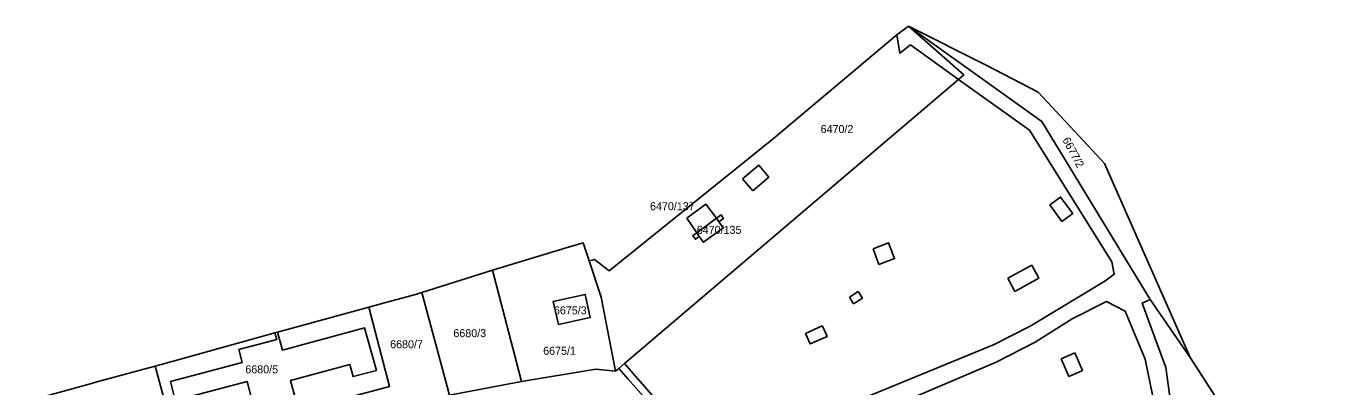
# Model space of a CAD drawing. Extents: x -266199 to -261993, y -1239047 to -1235108.
# Drawn here: x -263762 to -263435, y -1235757.7 to -1235667.6 of the extents above; entities that cross this region are included whole.
import ezdxf

# ---------------------------------------------------------------- set-up
doc = ezdxf.new("R2010")
doc.units = 0
for name, color, linetype in [('body_kn', 7, 'Continuous'), ('kladpar_druhypozemkov', 7, 'Continuous'), ('kladpar_hranice', 7, 'Continuous'), ('kladpar_parcelnecisla', 7, 'Continuous'), ('kladpar_plochy', 7, 'Continuous'), ('kladpar_sipky', 7, 'Continuous'), ('zappar_hrandruhpozemk', 7, 'Continuous')]:
    doc.layers.add(name, color=color, linetype=linetype)

msp = doc.modelspace()

# ---------------------------------------------------------------- linework, layer by layer
at = {"layer": 'body_kn'}
for p, q in [((-263544.41, -1235669.73), (-263544.41, -1235669.73)), ((-263544.41, -1235669.73), (-263544.41, -1235669.73)), ((-263541.53, -1235667.57), (-263541.53, -1235667.57)), ((-263541.53, -1235667.57), (-263541.53, -1235667.57)), ((-263541.05, -1235672.26), (-263541.05, -1235672.26)), ((-263543.64, -1235674.36), (-263543.64, -1235674.36)), ((-263527.67, -1235679.77), (-263527.67, -1235679.77)), ((-263522.1, -1235677.36), (-263522.1, -1235677.36)), ((-263528.99, -1235680.89), (-263528.99, -1235680.89)), ((-263528.99, -1235680.89), (-263528.99, -1235680.89)), ((-263509.13, -1235684.08), (-263509.13, -1235684.08)), ((-263508.24, -1235691.41), (-263508.24, -1235691.41)), ((-263575.26, -1235695.67), (-263575.26, -1235695.67)), ((-263511.25, -1235693.59), (-263511.25, -1235693.59)), ((-263578.93, -1235702.32), (-263578.93, -1235702.32)), ((-263494.46, -1235699.85), (-263494.46, -1235699.85)), ((-263492.55, -1235701.9), (-263492.55, -1235701.9)), ((-263582.95, -1235705.7), (-263582.95, -1235705.7)), ((-263582.95, -1235705.7), (-263582.95, -1235705.7)), ((-263576.41, -1235705.35), (-263576.41, -1235705.35)), ((-263580.4, -1235708.7), (-263580.4, -1235708.7)), ((-263592.11, -1235712.08), (-263592.11, -1235712.08)), ((-263506.17, -1235712.23), (-263506.17, -1235712.23)), ((-263503.5, -1235710.28), (-263503.5, -1235710.28)), ((-263596.91, -1235715.61), (-263596.91, -1235715.61)), ((-263596.91, -1235715.61), (-263596.91, -1235715.61)), ((-263589.52, -1235715.58), (-263589.52, -1235715.58)), ((-263589.52, -1235715.58), (-263589.52, -1235715.58)), ((-263588.35, -1235714.73), (-263588.35, -1235714.73)), ((-263587.7, -1235715.63), (-263587.7, -1235715.63)), ((-263500.47, -1235714.43), (-263500.47, -1235714.43)), ((-263588.9, -1235716.51), (-263588.9, -1235716.51)), ((-263587.81, -1235718.01), (-263587.81, -1235718.01)), ((-263503.17, -1235716.37), (-263503.17, -1235716.37)), ((-263503.17, -1235716.37), (-263503.17, -1235716.37)), ((-263622.79, -1235721.75), (-263622.79, -1235721.75)), ((-263595.42, -1235719.94), (-263595.42, -1235719.94)), ((-263594.77, -1235720.82), (-263594.77, -1235720.82)), ((-263594.39, -1235719.2), (-263594.39, -1235719.2)), ((-263594.39, -1235719.2), (-263594.39, -1235719.2)), ((-263593.83, -1235720.13), (-263593.83, -1235720.13)), ((-263592.76, -1235721.6), (-263592.76, -1235721.6)), ((-263546.54, -1235721.72), (-263546.54, -1235721.72)), ((-263627.04, -1235723.02), (-263627.04, -1235723.02)), ((-263550.33, -1235723.24), (-263550.33, -1235723.24)), ((-263545.01, -1235725.63), (-263545.01, -1235725.63)), ((-263645.42, -1235728.54), (-263645.42, -1235728.54)), ((-263645.42, -1235728.54), (-263645.42, -1235728.54)), ((-263621.28, -1235726.23), (-263621.28, -1235726.23)), ((-263621.28, -1235726.23), (-263621.28, -1235726.23)), ((-263620.53, -1235726.03), (-263620.53, -1235726.03)), ((-263619.96, -1235725.88), (-263619.96, -1235725.88)), ((-263616.31, -1235728.73), (-263616.31, -1235728.73)), ((-263548.93, -1235727.17), (-263548.93, -1235727.17)), ((-263548.93, -1235727.17), (-263548.93, -1235727.17)), ((-263510.66, -1235727.33), (-263510.66, -1235727.33)), ((-263490.71, -1235726.49), (-263490.71, -1235726.49)), ((-263516.68, -1235730.6), (-263516.68, -1235730.6)), ((-263508.99, -1235730.58), (-263508.99, -1235730.58)), ((-263492.43, -1235731.3), (-263492.43, -1235731.3)), ((-263490.11, -1235729.58), (-263490.11, -1235729.58)), ((-263664.65, -1235734.66), (-263664.65, -1235734.66)), ((-263663.09, -1235734.16), (-263663.09, -1235734.16)), ((-263663.09, -1235734.16), (-263663.09, -1235734.16)), ((-263622.29, -1235734.63), (-263622.29, -1235734.63)), ((-263622.29, -1235734.63), (-263622.29, -1235734.63)), ((-263618.29, -1235735.33), (-263618.29, -1235735.33)), ((-263556.25, -1235735.3), (-263556.25, -1235735.3)), ((-263554.06, -1235733.87), (-263554.06, -1235733.87)), ((-263514.91, -1235733.87), (-263514.91, -1235733.87)), ((-263514.91, -1235733.87), (-263514.91, -1235733.87)), ((-263676.38, -1235737.84), (-263676.38, -1235737.84)), ((-263672.4, -1235736.76), (-263672.4, -1235736.76)), ((-263630.28, -1235736.36), (-263630.28, -1235736.36)), ((-263555.27, -1235736.99), (-263555.27, -1235736.99)), ((-263555.27, -1235736.99), (-263555.27, -1235736.99)), ((-263553.03, -1235735.56), (-263553.03, -1235735.56)), ((-263492.02, -1235736.4), (-263492.02, -1235736.4)), ((-263483.11, -1235736.81), (-263483.11, -1235736.81)), ((-263481.16, -1235735.9), (-263481.16, -1235735.9)), ((-263621.08, -1235740.41), (-263621.08, -1235740.41)), ((-263500.63, -1235740.71), (-263500.63, -1235740.71)), ((-263487.38, -1235738.85), (-263487.38, -1235738.85)), ((-263699.81, -1235744.23), (-263699.81, -1235744.23)), ((-263699.16, -1235744.05), (-263699.16, -1235744.05)), ((-263693.7, -1235742.53), (-263693.7, -1235742.53)), ((-263677.42, -1235742.99), (-263677.42, -1235742.99)), ((-263628.96, -1235742.11), (-263628.96, -1235742.11)), ((-263567.22, -1235744.43), (-263567.22, -1235744.43)), ((-263567.22, -1235744.43), (-263567.22, -1235744.43)), ((-263563.05, -1235742.47), (-263563.05, -1235742.47)), ((-263562.84, -1235742.93), (-263562.84, -1235742.93)), ((-263561.85, -1235745.14), (-263561.85, -1235745.14)), ((-263511.14, -1235742.6), (-263511.14, -1235742.6)), ((-263708.85, -1235748.43), (-263708.85, -1235748.43)), ((-263699.37, -1235745.93), (-263699.37, -1235745.93)), ((-263697.95, -1235748.55), (-263697.95, -1235748.55)), ((-263566.11, -1235746.99), (-263566.11, -1235746.99)), ((-263520.12, -1235747.13), (-263520.12, -1235747.13)), ((-263509.88, -1235746.59), (-263509.88, -1235746.59)), ((-263723.4, -1235750.79), (-263723.4, -1235750.79)), ((-263708, -1235751.65), (-263708, -1235751.65)), ((-263519.61, -1235751.6), (-263519.61, -1235751.6)), ((-263503.34, -1235750.71), (-263503.34, -1235750.71)), ((-263503.34, -1235750.71), (-263503.34, -1235750.71)), ((-263499.96, -1235749.23), (-263499.96, -1235749.23)), ((-263482.36, -1235750.8), (-263482.36, -1235750.8)), ((-263471.12, -1235750.36), (-263471.12, -1235750.36)), ((-263729.77, -1235752.53), (-263729.77, -1235752.53)), ((-263729.77, -1235752.53), (-263729.77, -1235752.53)), ((-263681.11, -1235752.15), (-263681.11, -1235752.15)), ((-263674.46, -1235753.68), (-263674.46, -1235753.68)), ((-263619.66, -1235753.32), (-263619.66, -1235753.32)), ((-263614.69, -1235753.79), (-263614.69, -1235753.79)), ((-263614.69, -1235753.79), (-263614.69, -1235753.79)), ((-263613.92, -1235753.14), (-263613.92, -1235753.14)), ((-263613.92, -1235753.14), (-263613.92, -1235753.14)), ((-263612.49, -1235751.92), (-263612.49, -1235751.92)), ((-263612.49, -1235751.92), (-263612.49, -1235751.92)), ((-263499.69, -1235754.37), (-263499.69, -1235754.37)), ((-263498.03, -1235753.64), (-263498.03, -1235753.64)), ((-263477.26, -1235752.88), (-263477.26, -1235752.88)), ((-263745.66, -1235756.87), (-263745.66, -1235756.87)), ((-263744.32, -1235756.5), (-263744.32, -1235756.5)), ((-263725.93, -1235756.38), (-263725.93, -1235756.38)), ((-263706.75, -1235756.38), (-263706.75, -1235756.38)), ((-263695.92, -1235756.17), (-263695.92, -1235756.17)), ((-263680.27, -1235755.19), (-263680.27, -1235755.19)), ((-263671.15, -1235757.69), (-263671.15, -1235757.69)), ((-263638.19, -1235756.44), (-263638.19, -1235756.44)), ((-263611.54, -1235755.83), (-263611.54, -1235755.83)), ((-263609.19, -1235755.69), (-263609.19, -1235755.69)), ((-263501.42, -1235755.13), (-263501.42, -1235755.13))]:
    msp.add_line(p, q, dxfattribs=at)
at = {"layer": 'kladpar_druhypozemkov'}
for p, q in [((-263558.66, -1235691.69), (-263558.66, -1235691.69)), ((-263498.61, -1235698.96), (-263498.61, -1235698.96)), ((-263579.82, -1235705.75), (-263579.82, -1235705.75)), ((-263593.28, -1235715.41), (-263593.28, -1235715.41)), ((-263503.02, -1235713.35), (-263503.02, -1235713.35)), ((-263590.24, -1235717.9), (-263590.24, -1235717.9)), ((-263547.74, -1235724.66), (-263547.74, -1235724.66)), ((-263512.6, -1235730.61), (-263512.6, -1235730.61)), ((-263554.33, -1235735.22), (-263554.33, -1235735.22)), ((-263625.26, -1235737.02), (-263625.26, -1235737.02)), ((-263666.56, -1235745.29), (-263666.56, -1235745.29)), ((-263650.5, -1235742.91), (-263650.5, -1235742.91)), ((-263564.63, -1235744.59), (-263564.63, -1235744.59)), ((-263628.87, -1235747.41), (-263628.87, -1235747.41)), ((-263702.13, -1235751.86), (-263702.13, -1235751.86)), ((-263500.36, -1235752.78), (-263500.36, -1235752.78))]:
    msp.add_line(p, q, dxfattribs=at)
at = {"layer": 'kladpar_hranice'}
for points in [[(-263621.28, -1235726.23), (-263620.53, -1235726.03), (-263619.96, -1235725.88), (-263616.31, -1235728.73), (-263575.26, -1235695.67), (-263544.41, -1235669.73), (-263541.53, -1235667.57)], [(-263541.53, -1235667.57), (-263527.67, -1235679.77), (-263528.99, -1235680.89), (-263612.49, -1235751.92), (-263613.92, -1235753.14), (-263614.69, -1235753.79)], [(-263614.69, -1235753.79), (-263613.92, -1235753.14), (-263612.49, -1235751.92), (-263528.99, -1235680.89), (-263527.67, -1235679.77), (-263541.53, -1235667.57)], [(-263541.53, -1235667.57), (-263522.1, -1235677.36), (-263509.13, -1235684.08), (-263494.46, -1235699.85), (-263492.55, -1235701.9), (-263471.12, -1235750.36), (-263481.16, -1235735.9), (-263508.24, -1235691.41), (-263541.53, -1235667.57)], [(-263541.53, -1235667.57), (-263508.24, -1235691.41), (-263481.16, -1235735.9), (-263471.12, -1235750.36), (-263458.67, -1235769.77), (-263457.2, -1235774.82), (-263442.51, -1235813.86), (-263440.38, -1235820.49), (-263438.16, -1235827.4), (-263435, -1235836.54), (-263491.16, -1235848.11), (-263475.82, -1235844.22), (-263481.69, -1235826.93), (-263483.75, -1235820.84), (-263489.59, -1235803.64), (-263491.33, -1235798.48), (-263500.09, -1235772.67), (-263519.04, -1235777.56)], [(-263596.91, -1235715.61), (-263592.11, -1235712.08), (-263589.52, -1235715.58), (-263594.39, -1235719.2), (-263596.91, -1235715.61)], [(-263596.91, -1235715.61), (-263594.39, -1235719.2), (-263595.42, -1235719.94), (-263594.77, -1235720.82), (-263593.83, -1235720.13), (-263592.76, -1235721.6), (-263587.81, -1235718.01), (-263588.9, -1235716.51), (-263587.7, -1235715.63), (-263588.35, -1235714.73), (-263589.52, -1235715.58), (-263592.11, -1235712.08), (-263596.91, -1235715.61)], [(-263589.52, -1235715.58), (-263588.35, -1235714.73), (-263587.7, -1235715.63), (-263588.9, -1235716.51), (-263587.81, -1235718.01), (-263592.76, -1235721.6), (-263593.83, -1235720.13), (-263594.77, -1235720.82), (-263595.42, -1235719.94), (-263594.39, -1235719.2), (-263589.52, -1235715.58)], [(-263645.42, -1235728.54), (-263627.04, -1235723.02), (-263622.79, -1235721.75), (-263621.28, -1235726.23), (-263618.29, -1235735.33), (-263614.69, -1235753.79), (-263619.66, -1235753.32), (-263638.19, -1235756.44), (-263645.42, -1235728.54)], [(-263663.09, -1235734.16), (-263645.42, -1235728.54), (-263638.19, -1235756.44), (-263656.23, -1235759.78), (-263663.09, -1235734.16)], [(-263614.69, -1235753.79), (-263618.29, -1235735.33), (-263621.28, -1235726.23)], [(-263724.48, -1235771.89), (-263671.15, -1235757.69), (-263676.38, -1235737.84), (-263672.4, -1235736.76), (-263664.65, -1235734.66), (-263663.09, -1235734.16), (-263656.23, -1235759.78), (-263658.69, -1235760.24), (-263666.49, -1235762.13), (-263687.62, -1235767.25), (-263716.54, -1235775.23), (-263723.08, -1235776.97), (-263724.48, -1235771.89)], [(-263621.08, -1235740.41), (-263622.29, -1235734.63), (-263630.28, -1235736.36), (-263628.96, -1235742.11), (-263621.08, -1235740.41)], [(-263622.29, -1235734.63), (-263621.08, -1235740.41), (-263628.96, -1235742.11), (-263630.28, -1235736.36), (-263622.29, -1235734.63)], [(-263694.53, -1235761.37), (-263695.92, -1235756.17), (-263681.11, -1235752.15), (-263680.27, -1235755.19), (-263674.46, -1235753.68), (-263677.42, -1235742.99), (-263697.95, -1235748.55), (-263699.16, -1235744.05), (-263693.7, -1235742.53), (-263676.38, -1235737.84), (-263671.15, -1235757.69), (-263724.48, -1235771.89), (-263729.77, -1235752.53)], [(-263729.77, -1235752.53), (-263723.4, -1235750.79), (-263699.81, -1235744.23), (-263699.37, -1235745.93), (-263708.85, -1235748.43), (-263708, -1235751.65), (-263725.93, -1235756.38), (-263724.68, -1235761.37)], [(-263725.93, -1235756.38), (-263708, -1235751.65), (-263708.85, -1235748.43), (-263699.37, -1235745.93), (-263699.81, -1235744.23), (-263699.16, -1235744.05), (-263697.95, -1235748.55), (-263677.42, -1235742.99), (-263674.46, -1235753.68), (-263680.27, -1235755.19), (-263681.11, -1235752.15), (-263695.92, -1235756.17), (-263694.53, -1235761.37), (-263697.26, -1235762.1), (-263699.36, -1235762.66), (-263704.71, -1235764.11), (-263706.75, -1235756.38), (-263721.88, -1235760.37), (-263721.82, -1235760.62), (-263724.68, -1235761.37), (-263725.93, -1235756.38)], [(-263761.96, -1235761.38), (-263745.66, -1235756.87), (-263744.32, -1235756.5), (-263729.77, -1235752.53), (-263724.48, -1235771.89)], [(-263687.62, -1235767.25), (-263666.49, -1235762.13), (-263658.69, -1235760.24), (-263656.23, -1235759.78), (-263638.19, -1235756.44), (-263619.66, -1235753.32), (-263614.69, -1235753.79)], [(-263721.88, -1235760.37), (-263706.75, -1235756.38), (-263704.71, -1235764.11)]]:
    msp.add_lwpolyline(points, dxfattribs=at)
at = {"layer": 'kladpar_plochy'}
for p, q in [((-263575.26, -1235695.67), (-263544.41, -1235669.73)), ((-263544.41, -1235669.73), (-263541.53, -1235667.57)), ((-263541.53, -1235667.57), (-263527.67, -1235679.77)), ((-263527.67, -1235679.77), (-263541.53, -1235667.57)), ((-263541.53, -1235667.57), (-263508.24, -1235691.41)), ((-263527.67, -1235679.77), (-263528.99, -1235680.89)), ((-263528.99, -1235680.89), (-263527.67, -1235679.77)), ((-263528.99, -1235680.89), (-263612.49, -1235751.92)), ((-263612.49, -1235751.92), (-263528.99, -1235680.89)), ((-263508.24, -1235691.41), (-263481.16, -1235735.9)), ((-263616.31, -1235728.73), (-263575.26, -1235695.67)), ((-263592.11, -1235712.08), (-263596.91, -1235715.61)), ((-263589.52, -1235715.58), (-263592.11, -1235712.08)), ((-263596.91, -1235715.61), (-263594.39, -1235719.2)), ((-263588.35, -1235714.73), (-263589.52, -1235715.58)), ((-263588.9, -1235716.51), (-263587.7, -1235715.63)), ((-263587.7, -1235715.63), (-263588.35, -1235714.73)), ((-263592.76, -1235721.6), (-263587.81, -1235718.01)), ((-263587.81, -1235718.01), (-263588.9, -1235716.51)), ((-263627.04, -1235723.02), (-263622.79, -1235721.75)), ((-263622.79, -1235721.75), (-263621.28, -1235726.23)), ((-263594.39, -1235719.2), (-263595.42, -1235719.94)), ((-263595.42, -1235719.94), (-263594.77, -1235720.82)), ((-263594.77, -1235720.82), (-263593.83, -1235720.13)), ((-263593.83, -1235720.13), (-263592.76, -1235721.6)), ((-263645.42, -1235728.54), (-263627.04, -1235723.02)), ((-263638.19, -1235756.44), (-263645.42, -1235728.54)), ((-263621.28, -1235726.23), (-263620.53, -1235726.03)), ((-263621.28, -1235726.23), (-263618.29, -1235735.33)), ((-263618.29, -1235735.33), (-263621.28, -1235726.23)), ((-263620.53, -1235726.03), (-263619.96, -1235725.88)), ((-263619.96, -1235725.88), (-263616.31, -1235728.73)), ((-263622.29, -1235734.63), (-263630.28, -1235736.36)), ((-263621.08, -1235740.41), (-263622.29, -1235734.63)), ((-263618.29, -1235735.33), (-263614.69, -1235753.79)), ((-263614.69, -1235753.79), (-263618.29, -1235735.33)), ((-263630.28, -1235736.36), (-263628.96, -1235742.11)), ((-263481.16, -1235735.9), (-263471.12, -1235750.36)), ((-263628.96, -1235742.11), (-263621.08, -1235740.41)), ((-263471.12, -1235750.36), (-263458.67, -1235769.77)), ((-263619.66, -1235753.32), (-263638.19, -1235756.44)), ((-263638.19, -1235756.44), (-263619.66, -1235753.32)), ((-263614.69, -1235753.79), (-263619.66, -1235753.32)), ((-263619.66, -1235753.32), (-263614.69, -1235753.79)), ((-263613.92, -1235753.14), (-263614.69, -1235753.79)), ((-263614.69, -1235753.79), (-263613.92, -1235753.14)), ((-263612.49, -1235751.92), (-263613.92, -1235753.14)), ((-263613.92, -1235753.14), (-263612.49, -1235751.92)), ((-263656.23, -1235759.78), (-263638.19, -1235756.44))]:
    msp.add_line(p, q, dxfattribs=at)
for points in [[(-263541.53, -1235667.57), (-263522.1, -1235677.36), (-263509.13, -1235684.08), (-263494.46, -1235699.85), (-263492.55, -1235701.9), (-263471.12, -1235750.36), (-263481.16, -1235735.9), (-263508.24, -1235691.41)], [(-263596.91, -1235715.61), (-263592.11, -1235712.08), (-263589.52, -1235715.58), (-263594.39, -1235719.2)], [(-263589.52, -1235715.58), (-263588.35, -1235714.73), (-263587.7, -1235715.63), (-263588.9, -1235716.51), (-263587.81, -1235718.01), (-263592.76, -1235721.6), (-263593.83, -1235720.13), (-263594.77, -1235720.82), (-263595.42, -1235719.94), (-263594.39, -1235719.2)], [(-263663.09, -1235734.16), (-263645.42, -1235728.54), (-263638.19, -1235756.44), (-263656.23, -1235759.78)], [(-263724.48, -1235771.89), (-263671.15, -1235757.69), (-263676.38, -1235737.84), (-263672.4, -1235736.76), (-263664.65, -1235734.66), (-263663.09, -1235734.16), (-263656.23, -1235759.78), (-263658.69, -1235760.24), (-263666.49, -1235762.13), (-263687.62, -1235767.25), (-263716.54, -1235775.23), (-263723.08, -1235776.97)], [(-263622.29, -1235734.63), (-263621.08, -1235740.41), (-263628.96, -1235742.11), (-263630.28, -1235736.36)], [(-263725.93, -1235756.38), (-263708, -1235751.65), (-263708.85, -1235748.43), (-263699.37, -1235745.93), (-263699.81, -1235744.23), (-263699.16, -1235744.05), (-263697.95, -1235748.55), (-263677.42, -1235742.99), (-263674.46, -1235753.68), (-263680.27, -1235755.19), (-263681.11, -1235752.15), (-263695.92, -1235756.17), (-263694.53, -1235761.37), (-263697.26, -1235762.1), (-263699.36, -1235762.66), (-263704.71, -1235764.11), (-263706.75, -1235756.38), (-263721.88, -1235760.37), (-263721.82, -1235760.62), (-263724.68, -1235761.37)]]:
    msp.add_lwpolyline(points, close=True, dxfattribs=at)
for points in [[(-263694.53, -1235761.37), (-263695.92, -1235756.17), (-263681.11, -1235752.15), (-263680.27, -1235755.19), (-263674.46, -1235753.68), (-263677.42, -1235742.99), (-263697.95, -1235748.55), (-263699.16, -1235744.05), (-263693.7, -1235742.53), (-263676.38, -1235737.84), (-263671.15, -1235757.69), (-263724.48, -1235771.89), (-263729.77, -1235752.53), (-263723.4, -1235750.79), (-263699.81, -1235744.23), (-263699.37, -1235745.93), (-263708.85, -1235748.43), (-263708, -1235751.65), (-263725.93, -1235756.38), (-263724.68, -1235761.37)], [(-263761.96, -1235761.38), (-263745.66, -1235756.87), (-263744.32, -1235756.5), (-263729.77, -1235752.53), (-263724.48, -1235771.89)], [(-263721.88, -1235760.37), (-263706.75, -1235756.38), (-263704.71, -1235764.11)]]:
    msp.add_lwpolyline(points, dxfattribs=at)
at = {"layer": 'kladpar_sipky'}
msp.add_line((-263594.63, -1235716.59), (-263594.63, -1235716.59), dxfattribs=at)
at = {"layer": 'zappar_hrandruhpozemk'}
for p, q in [((-263541.05, -1235672.26), (-263528.99, -1235680.89)), ((-263528.99, -1235680.89), (-263511.25, -1235693.59)), ((-263511.25, -1235693.59), (-263490.71, -1235726.49)), ((-263582.95, -1235705.7), (-263580.4, -1235708.7)), ((-263580.4, -1235708.7), (-263576.41, -1235705.35)), ((-263506.17, -1235712.23), (-263503.17, -1235716.37)), ((-263589.52, -1235715.58), (-263588.9, -1235716.51)), ((-263594.39, -1235719.2), (-263593.83, -1235720.13)), ((-263550.33, -1235723.24), (-263548.93, -1235727.17)), ((-263510.66, -1235727.33), (-263516.68, -1235730.6)), ((-263516.68, -1235730.6), (-263514.91, -1235733.87)), ((-263554.06, -1235733.87), (-263556.25, -1235735.3)), ((-263556.25, -1235735.3), (-263555.27, -1235736.99)), ((-263563.05, -1235742.47), (-263567.22, -1235744.43)), ((-263499.96, -1235749.23), (-263503.34, -1235750.71)), ((-263498.03, -1235753.64), (-263499.96, -1235749.23)), ((-263613.92, -1235753.14), (-263611.54, -1235755.83)), ((-263612.49, -1235751.92), (-263609.19, -1235755.69)), ((-263611.54, -1235755.83), (-263592.55, -1235777.26)), ((-263609.19, -1235755.69), (-263590.97, -1235776.47))]:
    msp.add_line(p, q, dxfattribs=at)
for points in [[(-263544.41, -1235669.73), (-263543.64, -1235674.36), (-263541.05, -1235672.26)], [(-263576.41, -1235705.35), (-263578.93, -1235702.32), (-263582.95, -1235705.7)], [(-263503.17, -1235716.37), (-263500.47, -1235714.43), (-263503.5, -1235710.28), (-263506.17, -1235712.23)], [(-263548.93, -1235727.17), (-263545.01, -1235725.63), (-263546.54, -1235721.72), (-263550.33, -1235723.24)], [(-263490.71, -1235726.49), (-263490.11, -1235729.58), (-263492.43, -1235731.3), (-263511.14, -1235742.6), (-263520.12, -1235747.13), (-263551.94, -1235760.25)], [(-263514.91, -1235733.87), (-263508.99, -1235730.58), (-263510.66, -1235727.33)], [(-263555.27, -1235736.99), (-263553.03, -1235735.56), (-263554.06, -1235733.87)], [(-263479.81, -1235763.4), (-263482.36, -1235750.8), (-263487.38, -1235738.85), (-263492.02, -1235736.4), (-263500.63, -1235740.71), (-263509.88, -1235746.59), (-263519.61, -1235751.6), (-263551.28, -1235765.03)], [(-263475.89, -1235779.77), (-263475.64, -1235764.46), (-263477.26, -1235752.88), (-263483.11, -1235736.81), (-263481.16, -1235735.9)], [(-263567.22, -1235744.43), (-263566.11, -1235746.99), (-263561.85, -1235745.14), (-263562.84, -1235742.93), (-263563.05, -1235742.47)], [(-263503.34, -1235750.71), (-263501.42, -1235755.13), (-263499.69, -1235754.37), (-263498.03, -1235753.64)]]:
    msp.add_lwpolyline(points, dxfattribs=at)

# ---------------------------------------------------------------- texts
at = {"layer": 'kladpar_parcelnecisla'}
for s, p in [('6470/2', (-263563.47, -1235694.29)), ('6470/137', (-263606.09, -1235713.58)), ('6470/135', (-263594.41, -1235719.49)), ('6675/3', (-263630.11, -1235739.62)), ('6680/3', (-263655.22, -1235745.32)), ('6680/7', (-263671.02, -1235748.09)), ('6675/1', (-263632.79, -1235749.72)), ('6680/5', (-263707.21, -1235754.36))]:
    msp.add_text(s, height=2, dxfattribs=at).set_placement(p)
msp.add_text('6677/2', height=2, rotation=298, dxfattribs=at).set_placement((-263503.14, -1235695.97))

doc.saveas('drawing.dxf')
